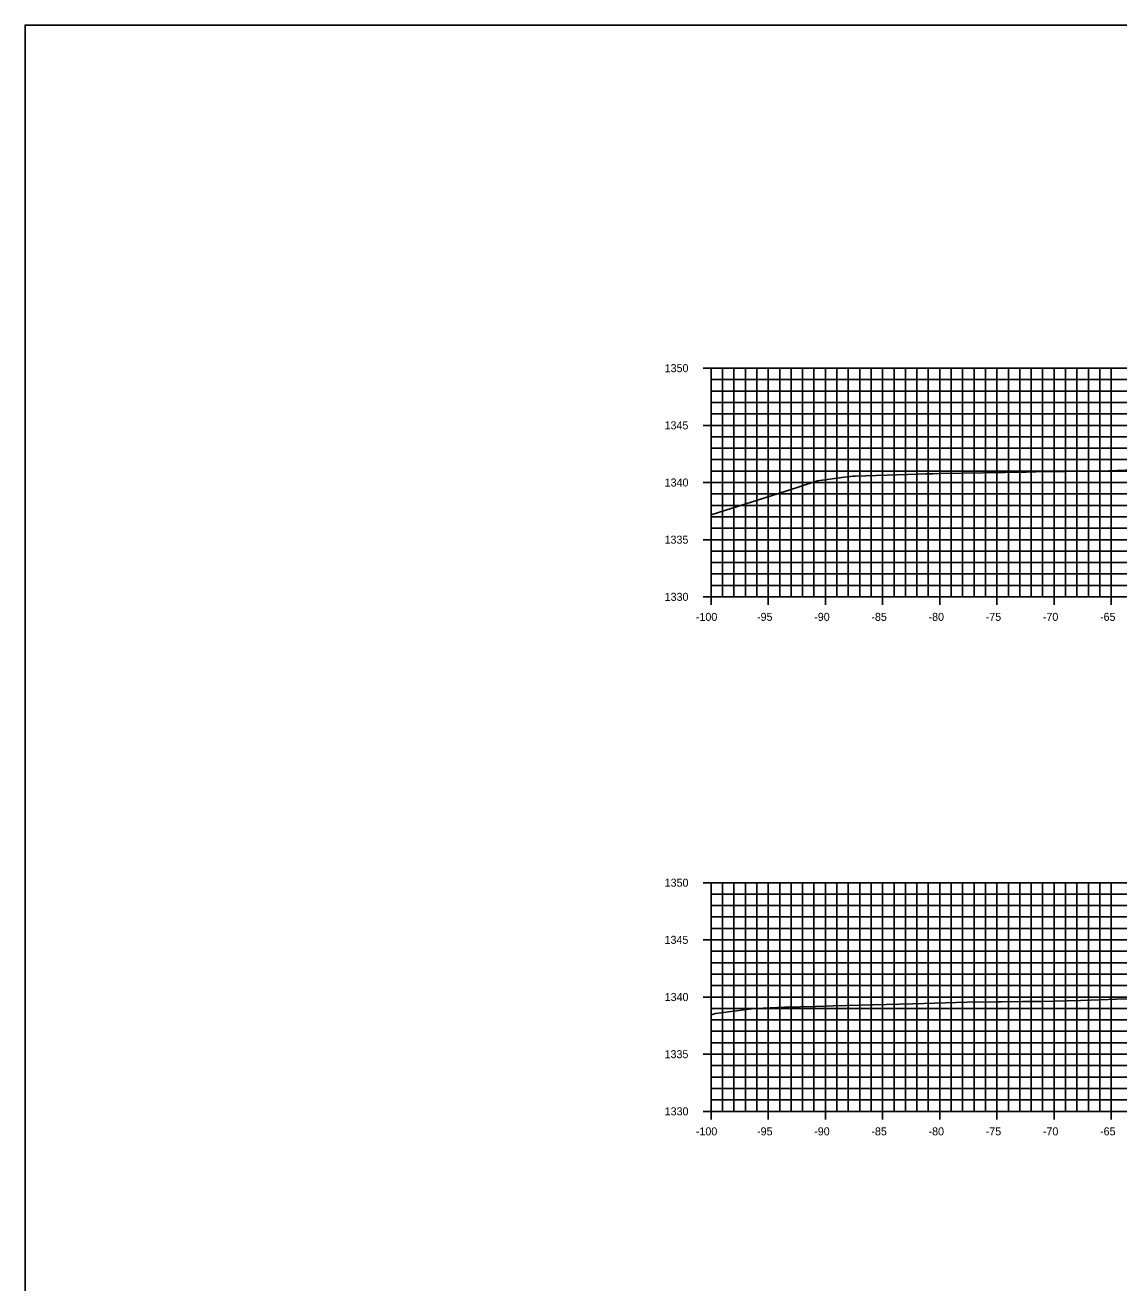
# Model space of a CAD drawing. Extents: x 674939 to 678919, y 750652 to 765176.
# Drawn here: x 678578.5 to 678674.2, y 752182.6 to 752292.6 of the extents above; entities that cross this region are included whole.
import ezdxf

# ---------------------------------------------------------------- set-up
doc = ezdxf.new("R2010")
doc.units = 0
for name, color, linetype in [('Level 10', 7, 'Continuous'), ('Level 20', 7, 'Continuous'), ('Level 4', 7, 'Continuous'), ('Level 8', 7, 'Continuous'), ('Level 9', 7, 'Continuous')]:
    doc.layers.add(name, color=color, linetype=linetype)

msp = doc.modelspace()

# ---------------------------------------------------------------- linework, layer by layer
at = {"layer": 'Level 10'}
for points in [[(678638.53, 752249.72), (678645.07, 752251.78), (678647.84, 752252.69), (678649.97, 752252.98), (678650.94, 752253.1), (678651.16, 752253.09), (678656.6, 752253.28), (678657.28, 752253.3), (678657.9, 752253.32), (678657.96, 752253.32), (678658.6, 752253.33), (678666.08, 752253.45), (678666.94, 752253.47), (678672.14, 752253.54), (678672.22, 752253.55), (678672.53, 752253.55), (678675.55, 752253.65)], [(678638.53, 752206), (678638.93, 752206.12), (678640.51, 752206.32), (678642.31, 752206.54), (678642.33, 752206.54), (678642.43, 752206.55), (678644.96, 752206.65), (678647.65, 752206.73), (678648.5, 752206.76), (678649.22, 752206.78), (678652.67, 752206.88), (678656.17, 752206.96), (678660.92, 752207.09), (678663.57, 752207.14), (678663.93, 752207.14), (678665.78, 752207.15), (678666.35, 752207.16), (678667.42, 752207.17), (678670.85, 752207.24), (678672.55, 752207.3), (678673.99, 752207.36), (678676.04, 752207.41)]]:
    msp.add_lwpolyline(points, dxfattribs=at)
at = {"layer": 'Level 20'}
for p, q in [((678638.53, 752262.55), (678838.53, 752262.55)), ((678638.53, 752242.55), (678638.53, 752262.55)), ((678639.53, 752242.55), (678639.53, 752262.55)), ((678640.53, 752242.55), (678640.53, 752262.55)), ((678641.53, 752242.55), (678641.53, 752262.55)), ((678642.53, 752242.55), (678642.53, 752262.55)), ((678643.53, 752242.55), (678643.53, 752262.55)), ((678644.53, 752242.55), (678644.53, 752262.55)), ((678645.53, 752242.55), (678645.53, 752262.55)), ((678646.53, 752242.55), (678646.53, 752262.55)), ((678647.53, 752242.55), (678647.53, 752262.55)), ((678648.53, 752242.55), (678648.53, 752262.55)), ((678649.53, 752242.55), (678649.53, 752262.55)), ((678650.53, 752242.55), (678650.53, 752262.55)), ((678651.53, 752242.55), (678651.53, 752262.55)), ((678652.53, 752242.55), (678652.53, 752262.55)), ((678653.53, 752242.55), (678653.53, 752262.55)), ((678654.53, 752242.55), (678654.53, 752262.55)), ((678655.53, 752242.55), (678655.53, 752262.55)), ((678656.53, 752242.55), (678656.53, 752262.55)), ((678657.53, 752242.55), (678657.53, 752262.55)), ((678658.53, 752242.55), (678658.53, 752262.55)), ((678659.53, 752242.55), (678659.53, 752262.55)), ((678660.53, 752242.55), (678660.53, 752262.55)), ((678661.53, 752242.55), (678661.53, 752262.55)), ((678662.53, 752242.55), (678662.53, 752262.55)), ((678663.53, 752242.55), (678663.53, 752262.55)), ((678664.53, 752242.55), (678664.53, 752262.55)), ((678665.53, 752242.55), (678665.53, 752262.55)), ((678666.53, 752242.55), (678666.53, 752262.55)), ((678667.53, 752242.55), (678667.53, 752262.55)), ((678668.53, 752242.55), (678668.53, 752262.55)), ((678669.53, 752242.55), (678669.53, 752262.55)), ((678670.53, 752242.55), (678670.53, 752262.55)), ((678671.53, 752242.55), (678671.53, 752262.55)), ((678672.53, 752242.55), (678672.53, 752262.55)), ((678673.53, 752242.55), (678673.53, 752262.55)), ((678638.53, 752261.55), (678838.53, 752261.55)), ((678638.53, 752260.55), (678838.53, 752260.55)), ((678638.53, 752259.55), (678838.53, 752259.55)), ((678638.53, 752258.55), (678838.53, 752258.55)), ((678638.53, 752257.55), (678838.53, 752257.55)), ((678638.53, 752256.55), (678838.53, 752256.55)), ((678638.53, 752255.55), (678838.53, 752255.55)), ((678638.53, 752254.55), (678838.53, 752254.55)), ((678638.53, 752253.55), (678838.53, 752253.55)), ((678638.53, 752252.55), (678838.53, 752252.55)), ((678638.53, 752251.55), (678838.53, 752251.55)), ((678638.53, 752250.55), (678838.53, 752250.55)), ((678638.53, 752249.55), (678838.53, 752249.55)), ((678638.53, 752248.55), (678838.53, 752248.55)), ((678638.53, 752247.55), (678838.53, 752247.55)), ((678638.53, 752246.55), (678838.53, 752246.55)), ((678638.53, 752245.55), (678838.53, 752245.55)), ((678638.53, 752244.55), (678838.53, 752244.55)), ((678638.53, 752243.55), (678838.53, 752243.55)), ((678638.53, 752242.55), (678838.53, 752242.55)), ((678638.53, 752217.55), (678838.53, 752217.55)), ((678638.53, 752197.55), (678638.53, 752217.55)), ((678639.53, 752197.55), (678639.53, 752217.55)), ((678640.53, 752197.55), (678640.53, 752217.55)), ((678641.53, 752197.55), (678641.53, 752217.55)), ((678642.53, 752197.55), (678642.53, 752217.55)), ((678643.53, 752197.55), (678643.53, 752217.55)), ((678644.53, 752197.55), (678644.53, 752217.55)), ((678645.53, 752197.55), (678645.53, 752217.55)), ((678646.53, 752197.55), (678646.53, 752217.55)), ((678647.53, 752197.55), (678647.53, 752217.55)), ((678648.53, 752197.55), (678648.53, 752217.55)), ((678649.53, 752197.55), (678649.53, 752217.55)), ((678650.53, 752197.55), (678650.53, 752217.55)), ((678651.53, 752197.55), (678651.53, 752217.55)), ((678652.53, 752197.55), (678652.53, 752217.55)), ((678653.53, 752197.55), (678653.53, 752217.55)), ((678654.53, 752197.55), (678654.53, 752217.55)), ((678655.53, 752197.55), (678655.53, 752217.55)), ((678656.53, 752197.55), (678656.53, 752217.55)), ((678657.53, 752197.55), (678657.53, 752217.55)), ((678658.53, 752197.55), (678658.53, 752217.55)), ((678659.53, 752197.55), (678659.53, 752217.55)), ((678660.53, 752197.55), (678660.53, 752217.55)), ((678661.53, 752197.55), (678661.53, 752217.55)), ((678662.53, 752197.55), (678662.53, 752217.55)), ((678663.53, 752197.55), (678663.53, 752217.55)), ((678664.53, 752197.55), (678664.53, 752217.55)), ((678665.53, 752197.55), (678665.53, 752217.55)), ((678666.53, 752197.55), (678666.53, 752217.55)), ((678667.53, 752197.55), (678667.53, 752217.55)), ((678668.53, 752197.55), (678668.53, 752217.55)), ((678669.53, 752197.55), (678669.53, 752217.55)), ((678670.53, 752197.55), (678670.53, 752217.55)), ((678671.53, 752197.55), (678671.53, 752217.55)), ((678672.53, 752197.55), (678672.53, 752217.55)), ((678673.53, 752197.55), (678673.53, 752217.55)), ((678638.53, 752216.55), (678838.53, 752216.55)), ((678638.53, 752215.55), (678838.53, 752215.55)), ((678638.53, 752214.55), (678838.53, 752214.55)), ((678638.53, 752213.55), (678838.53, 752213.55)), ((678638.53, 752212.55), (678838.53, 752212.55)), ((678638.53, 752211.55), (678838.53, 752211.55)), ((678638.53, 752210.55), (678838.53, 752210.55)), ((678638.53, 752209.55), (678838.53, 752209.55)), ((678638.53, 752208.55), (678838.53, 752208.55)), ((678638.53, 752207.55), (678838.53, 752207.55)), ((678638.53, 752206.55), (678838.53, 752206.55)), ((678638.53, 752205.55), (678838.53, 752205.55)), ((678638.53, 752204.55), (678838.53, 752204.55)), ((678638.53, 752203.55), (678838.53, 752203.55)), ((678638.53, 752202.55), (678838.53, 752202.55)), ((678638.53, 752201.55), (678838.53, 752201.55)), ((678638.53, 752200.55), (678838.53, 752200.55)), ((678638.53, 752199.55), (678838.53, 752199.55)), ((678638.53, 752198.55), (678838.53, 752198.55)), ((678638.53, 752197.55), (678838.53, 752197.55))]:
    msp.add_line(p, q, dxfattribs=at)
at = {"layer": 'Level 4'}
msp.add_lwpolyline([(678578.53, 752072.55), (678918.53, 752072.55), (678918.53, 752292.55), (678578.53, 752292.55)], close=True, dxfattribs=at)
at = {"layer": 'Level 8'}
for p, q in [((678637.83, 752262.55), (678639.23, 752262.55)), ((678638.53, 752242.55), (678638.53, 752262.55)), ((678638.53, 752261.55), (678638.88, 752261.55)), ((678638.53, 752260.55), (678638.88, 752260.55)), ((678638.53, 752259.55), (678638.88, 752259.55)), ((678638.53, 752258.55), (678638.88, 752258.55)), ((678637.83, 752257.55), (678639.23, 752257.55)), ((678638.53, 752256.55), (678638.88, 752256.55)), ((678638.53, 752255.55), (678638.88, 752255.55)), ((678638.53, 752254.55), (678638.88, 752254.55)), ((678638.53, 752253.55), (678638.88, 752253.55)), ((678637.83, 752252.55), (678639.23, 752252.55)), ((678638.53, 752251.55), (678638.88, 752251.55)), ((678638.53, 752250.55), (678638.88, 752250.55)), ((678638.53, 752249.55), (678638.88, 752249.55)), ((678638.53, 752248.55), (678638.88, 752248.55)), ((678637.83, 752247.55), (678639.23, 752247.55)), ((678638.53, 752246.55), (678638.88, 752246.55)), ((678638.53, 752245.55), (678638.88, 752245.55)), ((678638.53, 752244.55), (678638.88, 752244.55)), ((678638.53, 752243.55), (678638.88, 752243.55)), ((678638.53, 752241.85), (678638.53, 752243.25)), ((678643.53, 752241.85), (678643.53, 752243.25)), ((678648.53, 752241.85), (678648.53, 752243.25)), ((678653.53, 752241.85), (678653.53, 752243.25)), ((678658.53, 752241.85), (678658.53, 752243.25)), ((678663.53, 752241.85), (678663.53, 752243.25)), ((678668.53, 752241.85), (678668.53, 752243.25)), ((678673.53, 752241.85), (678673.53, 752243.25)), ((678637.83, 752242.55), (678639.23, 752242.55)), ((678638.53, 752242.55), (678838.53, 752242.55)), ((678637.83, 752217.55), (678639.23, 752217.55)), ((678638.53, 752197.55), (678638.53, 752217.55)), ((678638.53, 752216.55), (678638.88, 752216.55)), ((678638.53, 752215.55), (678638.88, 752215.55)), ((678638.53, 752214.55), (678638.88, 752214.55)), ((678638.53, 752213.55), (678638.88, 752213.55)), ((678637.83, 752212.55), (678639.23, 752212.55)), ((678638.53, 752211.55), (678638.88, 752211.55)), ((678638.53, 752210.55), (678638.88, 752210.55)), ((678638.53, 752209.55), (678638.88, 752209.55)), ((678637.83, 752207.55), (678639.23, 752207.55)), ((678638.53, 752208.55), (678638.88, 752208.55)), ((678638.53, 752206.55), (678638.88, 752206.55)), ((678638.53, 752205.55), (678638.88, 752205.55)), ((678638.53, 752204.55), (678638.88, 752204.55)), ((678638.53, 752203.55), (678638.88, 752203.55)), ((678637.83, 752202.55), (678639.23, 752202.55)), ((678638.53, 752201.55), (678638.88, 752201.55)), ((678638.53, 752200.55), (678638.88, 752200.55)), ((678638.53, 752199.55), (678638.88, 752199.55)), ((678638.53, 752198.55), (678638.88, 752198.55)), ((678638.53, 752196.85), (678638.53, 752198.25)), ((678643.53, 752196.85), (678643.53, 752198.25)), ((678648.53, 752196.85), (678648.53, 752198.25)), ((678653.53, 752196.85), (678653.53, 752198.25)), ((678658.53, 752196.85), (678658.53, 752198.25)), ((678663.53, 752196.85), (678663.53, 752198.25)), ((678668.53, 752196.85), (678668.53, 752198.25)), ((678673.53, 752196.85), (678673.53, 752198.25)), ((678637.83, 752197.55), (678639.23, 752197.55)), ((678638.53, 752197.55), (678838.53, 752197.55))]:
    msp.add_line(p, q, dxfattribs=at)

# ---------------------------------------------------------------- texts
at = {"layer": 'Level 9'}
for s, p in [('1350', (678634.47, 752262.2)), ('1345', (678634.46, 752257.2)), ('1340', (678634.47, 752252.2)), ('1335', (678634.46, 752247.2)), ('1330', (678634.47, 752242.2)), ('-100', (678637.2, 752240.45)), ('-95', (678642.55, 752240.45)), ('-90', (678647.55, 752240.45)), ('-85', (678652.55, 752240.45)), ('-80', (678657.55, 752240.45)), ('-75', (678662.55, 752240.45)), ('-70', (678667.55, 752240.45)), ('-65', (678672.55, 752240.45)), ('1350', (678634.47, 752217.2)), ('1345', (678634.46, 752212.2)), ('1340', (678634.47, 752207.2)), ('1335', (678634.46, 752202.2)), ('1330', (678634.47, 752197.2)), ('-100', (678637.2, 752195.45)), ('-95', (678642.55, 752195.45)), ('-90', (678647.55, 752195.45)), ('-85', (678652.55, 752195.45)), ('-80', (678657.55, 752195.45)), ('-75', (678662.55, 752195.45)), ('-70', (678667.55, 752195.45)), ('-65', (678672.55, 752195.45))]:
    msp.add_text(s, height=0.7, dxfattribs=at).set_placement(p)

doc.saveas('drawing.dxf')
